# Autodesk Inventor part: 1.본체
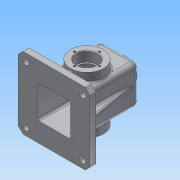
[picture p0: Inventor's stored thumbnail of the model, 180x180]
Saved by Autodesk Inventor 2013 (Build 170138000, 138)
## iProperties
Created: 2018-10
Part Number: 1.본체
Material: 알루미늄 6061
Document SubType Name: Modeling
Designer: Administrator
Density: 2.71 g/cm^3
Mass: 789.687 g
Surface Area: 898.798 cm^2
Volume: 291.397 cm^3
Author: Administrator
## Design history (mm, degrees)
sketch "스케치1"
  geometry: C1 r 27.5 at (0, 0); 1 further point
  constraints: 1 centre point, 1 coincident
  dimensions: "d0" = 55 diameter of C1
extrude "돌출1" new body sketch "스케치1" stored distance "d2" = 95; taper "d3" = 0 deg
node "작업 평면1"
sketch "스케치3"
  geometry: L1 (60, -60)-(-60, -60); L2 (-60, -60)-(-60, 60); L3 (-60, 60)-(60, 60); L4 (60, 60)-(60, -60); L5 (60, -60)-(-60, 60); L6 (-60, -60)-(60, 60); 1 further point
  constraints: 12 end point, 2 midpoint, 2 parallel, 1 horizontal, 1 perpendicular
  dimensions: "d5" = 120 distance of L1.start L1.end; "d7" = 120 distance of L1.end L2.end
extrude "돌출2" join sketch "스케치3" distance "d8" = 10; taper "d9" = 0 deg
sketch "스케치4"
  geometry: L1 (-32.5, 32.5)-(32.5, 32.5); L2 (32.5, 32.5)-(32.5, -32.5); L3 (32.5, -32.5)-(-32.5, -32.5); L4 (-32.5, -32.5)-(-32.5, 32.5); L5 (-32.5, 32.5)-(32.5, -32.5); L6 (32.5, 32.5)-(-32.5, -32.5); 1 further point
  constraints: 12 end point, 2 midpoint, 2 parallel, 1 horizontal, 1 perpendicular
  dimensions: "d10" = 65 distance of L1.start L1.end; "d12" = 65 distance of L1.end L2.end
extrude "돌출3" join sketch "스케치4" distance "d13" = 100; taper "d14" = 0 deg
chamfer "모따기1" distance "d15" = 8; stored, may be unused: second distance "d16" = 2, angle "d17" = 45 deg
sketch "스케치5"
  geometry: 3 further points
  dimensions: "d18" = 95 distance of point (47.5, 47.5) point (-47.5, 47.5); "d20" = 47.5 horizontal distance of point (-47.5, 47.5) point (0, 0); "d21" = 47.5 horizontal distance of point (0, 0) point (-47.5, 47.5); "d22" = 47.5 horizontal distance of point (0, 0) point (47.5, 47.5)
hole "구멍1" sketch "스케치5" at (-47.5, 47.5), (47.5, 47.5) diameter "d23" = 10; stored, may be unused: countersink angle "d27" = 90 deg, drill point angle "d29" = 118 deg; dims "d24" = 6, "d25" = 4, "d26" = 2, "d28" = 8
sketch "스케치6"
  geometry: L1 (-27.5, 27.5)-(27.5, 27.5); L2 (27.5, 27.5)-(27.5, -27.5); L3 (27.5, -27.5)-(-27.5, -27.5); L4 (-27.5, -27.5)-(-27.5, 27.5); L5 (-27.5, 27.5)-(27.5, -27.5); L6 (27.5, 27.5)-(-27.5, -27.5); 1 further point
  constraints: 12 end point, 2 midpoint, 2 parallel, 1 horizontal, 1 perpendicular
  dimensions: "d30" = 55 distance of L2.end L3.end; "d31" = 55 distance of L1.end L2.end
extrude "돌출4" cut sketch "스케치6" distance "d32" = 105; taper "d33" = 0 deg
sketch "스케치7"
  geometry: L1 (0, 0)-(21, 0); C1 r 27.5 at (0, 0) reference; 1 further point
  constraints: 2 end point, 1 coincident, 1 horizontal
  dimensions: "d34" = 21 distance of L1.start L1.end
hole "구멍2" sketch "스케치7" at (21, 0) diameter "d35" = 3.242; stored, may be unused: countersink angle "d39" = 90 deg, drill point angle "d41" = 118 deg; dims "d36" = 8, "d37" = 4, "d38" = 2, "d40" = 10
sketch "스케치9"
  geometry: C1 r 27.5 at (0, 0) reference
hole "구멍3" sketch "스케치9" at (0, 0) diameter "d45" = 30; stored, may be unused: countersink angle "d49" = 90 deg, drill point angle "d51" = 118 deg; dims "d46" = 8, "d47" = 35, "d48" = 17, "d50" = 10
sketch "스케치10"
  geometry: C1 r 15 at (0, 0) reference
hole "구멍4" sketch "스케치10" at (0, 0) diameter "d52" = 30; stored, may be unused: countersink angle "d56" = 90 deg, drill point angle "d58" = 118 deg; dims "d53" = 8, "d54" = 35, "d55" = 17, "d57" = 10
fillet "모깎기1" dims "d59" = 3
fillet "모깎기2" dims "d60" = 3
node "작업 평면2"
sketch "스케치11"
  geometry: C1 r 20 at (0, 0); 1 further point
  constraints: 1 centre point, 1 coincident
  dimensions: "d62" = 40 diameter of C1
extrude "돌출5" join sketch "스케치11" stored distance "d64" = 105; taper "d65" = 0 deg
feature "면 기울기1" dims angle "d66" = 7 deg
sketch "스케치13"
  geometry: L1 (32.5, 55)-(32.5, -45) reference; L2 (32.5, -45)-(60, -45) reference; L3 (60, -45)-(60, -55) reference; L4 (60, -55)-(27.5, -55) reference; L5 (27.5, -55)-(27.5, 47) reference; L6 (24.5, 50)-(-24.5, 50) reference; L7 (-18.772, 65)-(18.772, 65) reference; L8 (18.772, 65)-(20, 55) reference; L9 (20, 55)-(32.5, 55) reference; L10 (-32.5, -45)-(-32.5, 55) reference; L11 (-32.5, 55)-(-20, 55) reference; L12 (-20, 55)-(-18.772, 65) reference; L13 (-27.5, 47)-(-27.5, -55) reference; L14 (-27.5, -55)-(-60, -55) reference; L15 (-60, -55)-(-60, -45) reference; L16 (-60, -45)-(-32.5, -45) reference; L17 (-48, -45)-(-32.5, 42.905); A1 r 3 centre (24.5, 47) between (27.5, 47) and (24.5, 50) reference; A2 r 3 centre (-24.5, 47) between (-24.5, 50) and (-27.5, 47) reference; 1 further point
  constraints: 2 end point, 2 point on line
  dimensions: "d75" = 12 distance from line of L15 L17.start; "d76" = 100 deg angle of L16 L17
feature "리브1" sketch "스케치13" dims "d77" = 2, "d78" = 10, "d79" = 0, "d80" = 0, "d81" = 1, "d82" = 1
sketch "스케치14"
  geometry: L1 (-21, -36.526)-(-22.621, -37.5) reference; L2 (-22.621, -37.5)-(-22.621, -47.5) reference; L3 (-22.621, -47.5)-(-27.5, -47.5) reference; L4 (-27.5, -47.5)-(-27.5, -32.5) reference; L5 (-27.5, -32.5)-(-45, -32.5) reference; L6 (-45, -32.5)-(-45, -60) reference; L7 (-45, -60)-(-55, -60) reference; L8 (-55, -60)-(-55, -27.5) reference; L9 (-55, -27.5)-(-15, -27.5) reference; L10 (-15, -27.5)-(-15, -30.5) reference; L11 (-15, -30.5)-(-17.5, -30.5) reference; L12 (-17.5, -30.5)-(-17.5, -47.5) reference; L13 (-17.5, -47.5)-(-19.379, -47.5) reference; L14 (-19.379, -47.5)-(-19.379, -37.5) reference; L15 (-19.379, -37.5)-(-21, -36.526) reference; L16 (-22.621, 37.5)-(-21, 36.526) reference; L17 (-21, 36.526)-(-19.379, 37.5) reference; L18 (-19.379, 37.5)-(-19.379, 47.5) reference; L19 (-19.379, 47.5)-(-17.5, 47.5) reference; L20 (-17.5, 47.5)-(-17.5, 30.5) reference; L21 (-17.5, 30.5)-(-15, 30.5) reference; L22 (-15, 30.5)-(-15, 27.5) reference; L23 (-15, 27.5)-(-55, 27.5) reference; L24 (-55, 27.5)-(-55, 60) reference; L25 (-55, 60)-(-45, 60) reference; L26 (-45, 60)-(-45, 32.5) reference; L27 (-45, 32.5)-(-27.5, 32.5) reference; L28 (-27.5, 32.5)-(-27.5, 47.5) reference; L29 (-27.5, 47.5)-(-22.621, 47.5) reference; L30 (-22.621, 47.5)-(-22.621, 37.5) reference; L31 (27.5, 32.5)-(55, 32.5) reference; L32 (55, 32.5)-(55, 20) reference; L33 (55, 20)-(65, 18.772) reference; L34 (65, 18.772)-(65, -18.772) reference; L35 (50, -24.5)-(50, 24.5) reference; L36 (47, 27.5)-(15, 27.5) reference; L37 (15, 27.5)-(15, 30.5) reference; L38 (15, 30.5)-(17.5, 30.5) reference; L39 (17.5, 30.5)-(17.5, 47.5) reference; L40 (17.5, 47.5)-(19.379, 47.5) reference; L41 (19.379, 47.5)-(19.379, 37.5) reference; L42 (19.379, 37.5)-(21, 36.526) reference; L43 (21, 36.526)-(22.621, 37.5) reference; L44 (22.621, 37.5)-(22.621, 47.5) reference; L45 (22.621, 47.5)-(27.5, 47.5) reference; L46 (27.5, 47.5)-(27.5, 32.5) reference; L47 (55, -32.5)-(27.5, -32.5) reference; L48 (27.5, -32.5)-(27.5, -47.5) reference; L49 (27.5, -47.5)-(22.621, -47.5) reference; L50 (22.621, -47.5)-(22.621, -37.5) reference; L51 (22.621, -37.5)-(21, -36.526) reference; L52 (21, -36.526)-(19.379, -37.5) reference; L53 (19.379, -37.5)-(19.379, -47.5) reference; L54 (19.379, -47.5)-(17.5, -47.5) reference; L55 (17.5, -47.5)-(17.5, -30.5) reference; L56 (17.5, -30.5)-(15, -30.5) reference; L57 (15, -30.5)-(15, -27.5) reference; L58 (15, -27.5)-(47, -27.5) reference; L59 (65, -18.772)-(55, -20) reference; L60 (55, -20)-(55, -32.5) reference; L61 (-45, 42.5)-(-30.759, 42.5); A1 r 3 centre (47, 24.5) between (50, 24.5) and (47, 27.5) reference; A2 r 3 centre (47, -24.5) between (47, -27.5) and (50, -24.5) reference; 1 further point
  constraints: 2 end point, 1 perpendicular, 1 point on line
  dimensions: "d83" = 15 distance between parallel lines of L23 L61
feature "리브2" sketch "스케치14" dims "d84" = 2, "d85" = 6, "d86" = 0, "d87" = 0, "d88" = 1, "d89" = 1
fillet "모깎기3" dims "d90" = 3
fillet "모깎기4" dims "d91" = 0.3
fillet "모깎기5" dims "d92" = 8
fillet "모깎기6" dims "d93" = 8
fillet "모깎기7" dims "d94" = 3
fillet "모깎기8" dims "d95" = 3
fillet "모깎기9" dims "d96" = 3
fillet "모깎기10" dims "d97" = 1
chamfer "모따기2" distance "d98" = 1; stored, may be unused: second distance "d99" = 2, angle "d100" = 45 deg
sketch "스케치15"
  geometry: L1 (-8, 0)-(-8, -91) reference; L2 (5.728, 18)-(43.272, 18) reference; 1 further point
  constraints: 1 other
  dimensions: "d101" = 32.5 distance from line of point (24.5, -8) L1; "d102" = 26 distance from line of L2 point (24.5, -8)
feature "엠보싱1" sketch "스케치15" dims "d14" = 0, "d103" = 0.5, "d104" = 0
fillet "모깎기11" dims "d105" = 3
hole "구멍5" diameter "d111" = 22.835; stored, may be unused: countersink angle "d115" = 90 deg, drill point angle "d117" = 118 deg; dims "d109" = 10, "d110" = 10, "d112" = 30, "d113" = 35, "d114" = 17, "d116" = 10
chamfer "모따기4" distance "d118" = 1; stored, may be unused: second distance "d119" = 2, angle "d120" = 45 deg
node "솔리드1"
mirror "대칭1"
pattern_circular "원형 패턴1" dims angle "d43" = 360 deg
mirror "대칭2"
mirror "대칭3"
mirror "대칭4"
node "절단 모서리 투영1"
node "절단 모서리 투영2"
other parameters: "d4" = -55
